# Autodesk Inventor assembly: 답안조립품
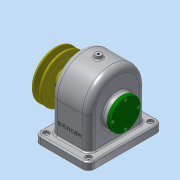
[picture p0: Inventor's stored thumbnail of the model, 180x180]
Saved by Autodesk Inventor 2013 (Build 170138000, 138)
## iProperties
Created: 2016-10
Part Number: 답안조립품
Document SubType Name: Assembly
Designer: Administrator
Author: Administrator
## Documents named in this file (15)
- C:\Users\Administrator\Desktop\461008V1030\답안조립품.iam
- C:\Users\Administrator\Desktop\461008V1030\본체.ipt
- C:\Users\Administrator\Desktop\461008V1030\앞커버.ipt
- C:\Users\Administrator\Desktop\461008V1030\뒤커버.ipt
- C:\Users\Administrator\Desktop\461008V1030\베어링 6203.ipt
- C:\Users\Administrator\Desktop\461008V1030\볼트 M3 x 10.ipt
- C:\Users\Administrator\Desktop\461008V1030\축.ipt
- C:\Users\Administrator\Desktop\461008V1030\키 - 6 x 6 x 22.ipt
- C:\Users\Administrator\Desktop\461008V1030\키 - 5 x 5 x 18.ipt
- C:\Users\Administrator\Desktop\461008V1030\부시.ipt
- C:\Users\Administrator\Desktop\461008V1030\오일씰 28 40 8.ipt
- C:\Users\Administrator\Desktop\461008V1030\V-벨트풀리.ipt
- C:\Users\Administrator\Desktop\461008V1030\멈춤나사 - M4x10.ipt
- C:\Users\Administrator\Desktop\461008V1030\스퍼기어.ipt
- C:\Users\Administrator\Desktop\461008V1030\볼트 M3 x 8.ipt
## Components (9 placed, 3 different names)
1. V-벨트풀리:1 — 각도:3
2. ISO 4762 M3 x 8:1
3. ISO 4762 M3 x 8:2
4. ISO 4762 M3 x 8:3
5. ISO 4762 M3 x 8:4
6. ISO 4762 M3 x 10:1
7. ISO 4762 M3 x 10:2
8. ISO 4762 M3 x 10:3
9. ISO 4762 M3 x 10:4
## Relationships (1: Angle 1)
- 각도:3 [Angle]: V-벨트풀리:1
